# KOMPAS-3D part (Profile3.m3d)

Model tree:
1. Plane XY
2. Plane ZX
3. Plane ZY
4. X Axis
5. Y Axis
6. Z Axis
7. Origin
8. Sketch:1
9. Extrude:1
     Wall Thickness 1 = 1; Wall Thickness 2 = 8; Distance 1 = 2560; Distance 2 = 10
10. Three Point Plane:1
11. Three Point Plane:2
12. Sketch:2
13. Extrude:2
     Wall Thickness 1 = 1; Wall Thickness 2 = 8; Distance 1 = 111; Distance 2 = 10
14. Sketch:3
15. Extrude:3
     Wall Thickness 1 = 1; Wall Thickness 2 = 8; Distance 1 = 111; Distance 2 = 10

Referenced files in D:\Documents and Settings\kashirsky\Рабочий стол\Seminar\: Cottage_balcony.a3d
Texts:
  Steel DIN 17102
  Three Point Plane
  Plane at Angle
  Line and Point Plane
  Axis through Two Vertices
  Axis of Feature
  Axis of Conical Surface
  Axis through Edge
  Trim by Surface
  Trim by Sketch
  Feature with No History
  Intersection Axis of Two Planes
  Two Line Plane
  Line and Face Plane
  Bend by line
  Hole in sheet body
  Cut in sheet body
  Point in CM
  Linear Dimension from Line to Point
  Surface Finish Symbol
  Geometric Tolerance Symbol
  Leader #1
  Leader #2
  Leader #3
  Shape Deviations and Datum
  Node point number
  Mark of coordination axis
  Node point designation
  Mark/Reference designation with leader
  Mark/reference designation on line
  Mark/Reference designation without leader
  CONTINUOUS_RGB_255_0_0_THICK_0.18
